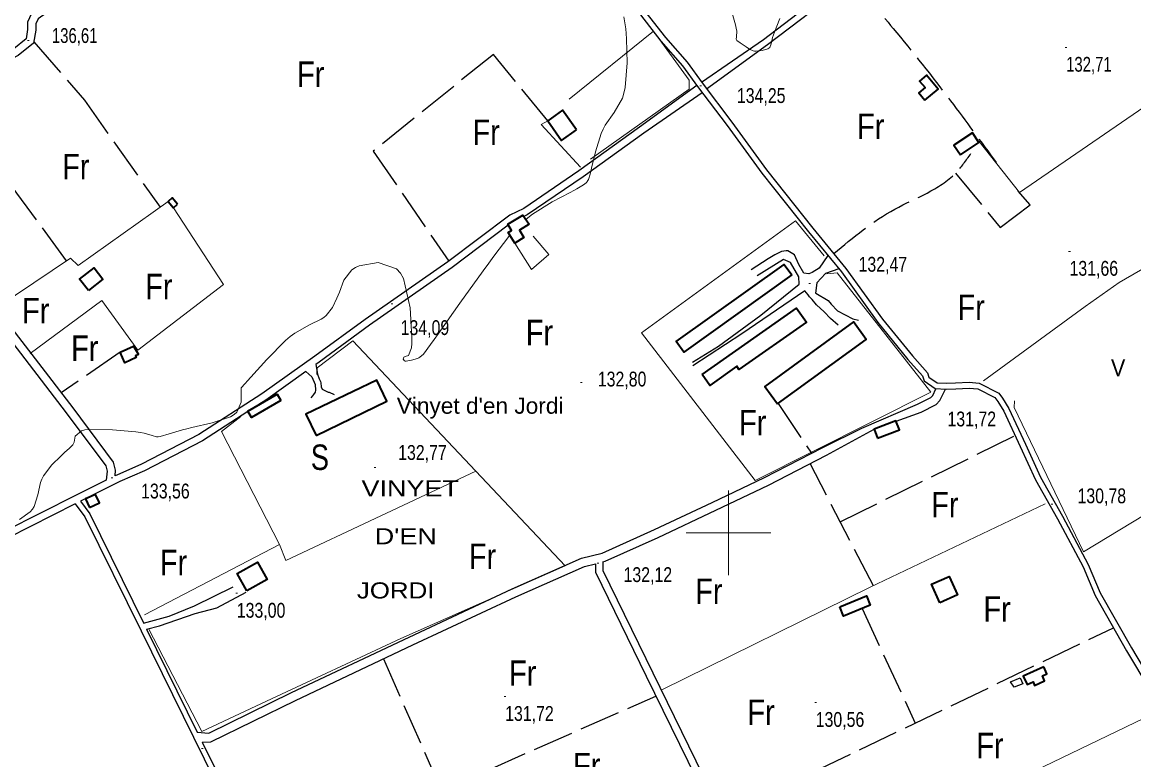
# Model space of a CAD drawing. Extents: x 483855 to 488461, y 4388206 to 4391419.
# Drawn here: x 485084 to 485739, y 4390366 to 4390801 of the extents above; entities that cross this region are included whole.
import ezdxf
from ezdxf.enums import TextEntityAlignment as Align

# ---------------------------------------------------------------- set-up
doc = ezdxf.new("R2010")
doc.units = 0
doc.header["$LTSCALE"] = 4
doc.linetypes.add('LONG_DASHED', pattern=[7.5, 6, -1.5])
for name, color, linetype, lineweight in [('1', 7, 'Continuous', 13), ('21', 7, 'Continuous', 25), ('25', 7, 'LONG_DASHED', 25), ('36', 7, 'Continuous', 25), ('38', 7, 'Continuous', 25), ('47', 7, 'Continuous', 35), ('51', 7, 'Continuous', 13), ('7', 7, 'Continuous', 13), ('9', 7, 'Continuous', 13)]:
    doc.layers.add(name, color=color, linetype=linetype, lineweight=lineweight)
doc.layers.add('31', color=7, linetype='Continuous')
doc.layers.add('5', color=7, linetype='Continuous')

msp = doc.modelspace()

# ---------------------------------------------------------------- linework, layer by layer
at = {"layer": '1'}
for p, q in [((485500, 4390525), (485500, 4390475)), ((485475, 4390500), (485525, 4390500))]:
    msp.add_line(p, q, dxfattribs=at)
at = {"layer": '21'}
msp.add_lwpolyline([(485673.31, 4390410.9), (485668.29, 4390408.94), (485666.19, 4390412.17), (485671.88, 4390414.43)], close=True, dxfattribs=at)
at = {"layer": '25'}
for p, q in [((485110.05, 4390660.3), (485037.72, 4390758.71)), ((485141.55, 4390606.36), (485106.86, 4390582.49)), ((485529.18, 4390576.09), (485548.8, 4390546.83)), ((485565.83, 4390506.52), (485668.86, 4390557.26)), ((485585.32, 4390468.79), (485548.13, 4390540.73)), ((485578.76, 4390455.3), (485610, 4390387.84)), ((485496.08, 4390333.01), (485726.76, 4390444.04)), ((485330.9, 4390348.01), (485457.19, 4390403.79))]:
    msp.add_line(p, q, dxfattribs=at)
for points in [[(485090.71, 4390789.32), (485120.57, 4390754.91), (485165.17, 4390691.87)], [(485393.49, 4390742.76), (485361.47, 4390781.94), (485290.75, 4390724.89), (485335.22, 4390660.14)], [(485633.81, 4390712.02), (485659.97, 4390679.88), (485677.65, 4390693.19), (485670.73, 4390701.38)], [(485296.72, 4390425.72), (485330.9, 4390348.01), (485230.08, 4390296.09)]]:
    msp.add_lwpolyline(points, dxfattribs=at)
at = {"layer": '36'}
for points in [[(485441.39, 4390813.87), (485460.18, 4390789.75), (485472.96, 4390775.14), (485481.68, 4390763.08), (485499.27, 4390739.93), (485519.72, 4390711.91), (485547.08, 4390677.37), (485566.47, 4390653.7), (485587.9, 4390623.88), (485605.71, 4390602.08), (485614.21, 4390592.42), (485615.19, 4390589.49), (485621.72, 4390584.93), (485628.17, 4390584.64), (485633.87, 4390584.87), (485641.67, 4390585.26), (485646.78, 4390584.82), (485656.91, 4390579.66), (485658.56, 4390577.34), (485662.1, 4390571.64), (485671.89, 4390550.8), (485680.77, 4390531.24), (485693.78, 4390508.15), (485708.83, 4390479.9), (485715.91, 4390463.03), (485734.49, 4390430.51), (485748.11, 4390407.42)], [(485443.99, 4390816.14), (485462.83, 4390791.94), (485475.66, 4390777.29), (485484.44, 4390765.13), (485502.03, 4390741.99), (485522.46, 4390713.99), (485549.76, 4390679.53), (485569.2, 4390655.8), (485590.63, 4390625.97), (485608.34, 4390604.31), (485617.25, 4390594.17), (485618.09, 4390591.66), (485622.87, 4390588.32), (485628.18, 4390588.08), (485633.71, 4390588.31), (485641.73, 4390588.71), (485647.74, 4390588.19), (485659.22, 4390582.34), (485661.43, 4390579.25), (485665.13, 4390573.29), (485675.01, 4390552.24), (485683.84, 4390532.8), (485696.8, 4390509.8), (485711.94, 4390481.38), (485719, 4390464.56), (485737.47, 4390432.24), (485751.16, 4390409.03)], [(485443.99, 4390816.14), (485462.83, 4390791.94), (485475.66, 4390777.29), (485484.44, 4390765.13), (485502.03, 4390741.99), (485522.46, 4390713.99), (485549.76, 4390679.53), (485569.2, 4390655.8), (485590.63, 4390625.97), (485608.34, 4390604.31), (485617.25, 4390594.17), (485618.09, 4390591.66), (485622.87, 4390588.32), (485628.18, 4390588.08), (485633.71, 4390588.31), (485641.73, 4390588.71), (485647.74, 4390588.19), (485659.22, 4390582.34), (485661.43, 4390579.25), (485665.13, 4390573.29), (485675.01, 4390552.24), (485683.84, 4390532.8), (485696.8, 4390509.8), (485711.94, 4390481.38), (485719, 4390464.56), (485737.47, 4390432.24), (485751.16, 4390409.03)]]:
    msp.add_lwpolyline(points, dxfattribs=at)
at = {"layer": '38'}
msp.add_line((485157.19, 4390443.11), (485186.98, 4390382.58), dxfattribs=at)
for points in [[(485311.17, 4390959), (485273.41, 4390932.69), (485228.9, 4390902.16), (485184.76, 4390872.9), (485152.54, 4390850.87), (485124.97, 4390831.4), (485089.4, 4390806.02), (485087.11, 4390800.89), (485087.12, 4390796.59), (485086.17, 4390791.06), (485078.91, 4390785.27), (485050.68, 4390770.45), (485010.21, 4390750.37), (484988.21, 4390740.68), (484987.9, 4390738), (484987.22, 4390733.35), (484988.91, 4390729.82), (485021.04, 4390685.75), (485063.44, 4390630.98), (485109.89, 4390570.75), (485133.09, 4390539.47), (485133.9, 4390536.4), (485133.44, 4390530.95)], [(485484.09, 4390765.62), (485520.58, 4390790.78), (485565.16, 4390824.83), (485603.51, 4390855.05), (485644.49, 4390882.72), (485686.53, 4390910.77), (485710.42, 4390927.08), (485719.98, 4390931.28), (485725.74, 4390931), (485729.29, 4390927.74), (485765.68, 4390872.99), (485798.54, 4390825.11), (485825.46, 4390783.37), (485847.11, 4390755.57), (485864.56, 4390728.75), (485879.65, 4390706.38)], [(485487.07, 4390761.68), (485522.88, 4390787.67), (485567.53, 4390821.78), (485605.79, 4390851.92), (485646.65, 4390879.5), (485688.7, 4390907.56), (485712.31, 4390923.68), (485720.7, 4390927.37), (485724.15, 4390927.2), (485726.32, 4390925.21), (485762.47, 4390870.82), (485795.31, 4390822.96), (485822.3, 4390781.12), (485843.95, 4390753.32), (485861.33, 4390726.61), (485876.45, 4390704.2), (485896.67, 4390661.98), (485921.44, 4390613.92), (485950.81, 4390554.58), (485972.61, 4390514.7)], [(485146.87, 4390841.02), (485127.73, 4390827.51), (485093.22, 4390802.89), (485091.88, 4390799.88), (485091.89, 4390796.19), (485090.56, 4390788.47), (485081.53, 4390781.26), (485052.84, 4390766.21), (485012.23, 4390746.05), (484992.63, 4390737.42), (484992.63, 4390737.39), (484992.15, 4390734.1), (484993.02, 4390732.28), (485024.85, 4390688.62), (485067.21, 4390633.89), (485113.69, 4390573.63), (485137.47, 4390541.57), (485138.72, 4390536.82), (485138.44, 4390533.46)], [(485481.25, 4390763.68), (485447.59, 4390739.09), (485411.85, 4390713.31), (485379.33, 4390691.05), (485371.08, 4390687.21), (485334.74, 4390659.77), (485285.97, 4390625.78), (485256.3, 4390604.06), (485224.98, 4390581.8), (485188.03, 4390557.89), (485154.16, 4390540.35), (485139.61, 4390534.03), (485138.44, 4390533.46)], [(485484.53, 4390759.34), (485450.1, 4390735.6), (485414.32, 4390709.79), (485381.47, 4390687.3), (485379.43, 4390686.35)], [(485370.25, 4390681.19), (485337.27, 4390656.29), (485288.47, 4390622.28), (485258.82, 4390600.57), (485256.81, 4390599.14)], [(485558.57, 4390663.35), (485553.34, 4390655.85), (485549.22, 4390653.3), (485547.27, 4390652.69), (485544.42, 4390652.99), (485541.34, 4390658.01), (485538.85, 4390663.78), (485534.95, 4390666.17), (485533.97, 4390666.17), (485531.27, 4390665.79), (485527.3, 4390663.76), (485523.33, 4390661.5), (485513.36, 4390655.04)], [(485478.79, 4390600.6), (485494.08, 4390610.07), (485519.03, 4390628.19), (485541.58, 4390646.61), (485541.35, 4390650.88), (485536.61, 4390659.28), (485532.4, 4390660.99), (485516.89, 4390651.52)], [(485564.95, 4390655.57), (485557.17, 4390652.71), (485551.93, 4390647.3), (485551.19, 4390641.3), (485551.42, 4390641.22), (485558.7, 4390636.81), (485560.43, 4390634.79), (485564.11, 4390630.82), (485573.19, 4390626.1), (485576.5, 4390625.28)], [(485564.57, 4390622.41), (485560.14, 4390626.31), (485556.31, 4390630.28), (485551.88, 4390634.32), (485549.25, 4390637.39), (485547.67, 4390639.12), (485546.84, 4390640.24), (485545.04, 4390642.56), (485507.8, 4390617.15), (485479.02, 4390598.35)], [(485256.81, 4390599.14), (485257.81, 4390593.48), (485258.94, 4390590.78), (485259.7, 4390589.06), (485259.85, 4390588.31), (485260.08, 4390585.98), (485260.68, 4390584.71), (485264.21, 4390582.92), (485264.66, 4390582.77), (485267.73, 4390581.57)], [(485251.05, 4390595.05), (485227.4, 4390578.24), (485223.4, 4390575.65)], [(485251.05, 4390595.05), (485254.52, 4390591.83), (485256.4, 4390587.48), (485256.63, 4390584.1), (485256.48, 4390582.9), (485255.51, 4390581.55), (485254.98, 4390580.73), (485253.86, 4390579.52)], [(485186.98, 4390382.58), (485193.76, 4390381.82), (485242.63, 4390405.8), (485311.94, 4390438.57), (485372.63, 4390466.9), (485413.42, 4390485.02), (485425.63, 4390488.04), (485456.49, 4390501.91), (485490.32, 4390517.92), (485521.28, 4390532.56), (485555.5, 4390550.3), (485578.44, 4390561.59), (485611.32, 4390575.74), (485619.18, 4390579.72), (485620.3, 4390580.88), (485622.05, 4390584.92)], [(485598.68, 4390565.7), (485613.49, 4390571.11), (485622.26, 4390575.55), (485624.51, 4390577.88), (485627.82, 4390584.67)], [(485216.92, 4390571.46), (485190.19, 4390554.16), (485156.01, 4390536.46), (485141.43, 4390530.13), (485118.17, 4390518.56)], [(485425.89, 4390482.84), (485427.3, 4390483.19), (485458.63, 4390497.27), (485492.51, 4390513.3), (485523.55, 4390527.98), (485557.8, 4390545.74), (485585.79, 4390560.99)], [(485133.44, 4390530.95), (485115.7, 4390522.14), (485073.73, 4390500.91), (485031.83, 4390479.77), (485010.32, 4390468.03), (485001.93, 4390465.01), (484981.84, 4390460.24)], [(485115.19, 4390517.05), (485075.67, 4390497.07), (485033.83, 4390475.96), (485012.09, 4390464.09), (485003.16, 4390460.88), (484947.91, 4390447.77), (484892.69, 4390433.86), (484854.23, 4390425.4), (484823.48, 4390418.15)], [(485115.19, 4390517.05), (485120.9, 4390509.39), (485153.94, 4390442.23), (485197.14, 4390354.46), (485231.39, 4390286.11), (485274.74, 4390199.39), (485308.3, 4390134.85), (485322.07, 4390107.8), (485344.04, 4390065.9), (485357.15, 4390034.19)], [(485118.17, 4390518.56), (485123.73, 4390511.12), (485155.3, 4390446.94)], [(485189.92, 4390376.61), (485195.01, 4390376.74), (485244.85, 4390401.2), (485314.11, 4390433.94), (485374.75, 4390462.25), (485415.08, 4390480.17), (485421.55, 4390481.77)], [(485421.55, 4390481.77), (485421.57, 4390476.82), (485451.45, 4390415.49), (485480.94, 4390355.34), (485505.34, 4390302.62), (485511.39, 4390287.91), (485519.02, 4390277.43)], [(485425.89, 4390482.84), (485425.92, 4390477.83), (485455.36, 4390417.4), (485484.87, 4390357.21), (485509.33, 4390304.37), (485515.21, 4390290.05), (485521.05, 4390282.03), (485536.34, 4390285.07), (485552.75, 4390289.3), (485561.08, 4390288.86), (485572.58, 4390290.77), (485576.97, 4390293.53), (485583.14, 4390290.64), (485593.96, 4390282.92), (485604.49, 4390279.94)], [(485155.39, 4390446.78), (485170.58, 4390450.81), (485185.5, 4390456.99), (485208.13, 4390468.13)], [(485157.19, 4390443.11), (485164.74, 4390445.1), (485185.88, 4390452.41), (485198.63, 4390455.81), (485215.94, 4390464.99)], [(485189.92, 4390376.61), (485200.1, 4390355.93), (485234.34, 4390287.59), (485277.68, 4390200.89), (485311.23, 4390136.36), (485325, 4390109.31), (485347.03, 4390067.3), (485360.2, 4390035.45)]]:
    msp.add_lwpolyline(points, dxfattribs=at)
at = {"layer": '38', "linetype": 'LONG_DASHED'}
for points in [[(485572.68, 4390825.83), (485596.99, 4390797.25), (485630.74, 4390754.62), (485657.73, 4390718.13)], [(485562, 4390664.6), (485597.99, 4390690.73), (485633.81, 4390712.02), (485642.8, 4390723.51)], [(485014.04, 4390465.16), (485018.06, 4390459.11), (485044.44, 4390383.92), (485062.76, 4390327.24), (485083.13, 4390259.98), (485109.98, 4390167.39)]]:
    msp.add_spline(points, degree=3, dxfattribs=at)
at = {"layer": '47'}
for points in [[(485615.74, 4390755.05), (485623.46, 4390761.51), (485616.67, 4390769.61), (485612.57, 4390766.17), (485615.78, 4390762.34), (485612.13, 4390759.32)], [(485410.46, 4390737.46), (485402.25, 4390749), (485393.49, 4390742.76), (485401.7, 4390731.22)], [(485636.57, 4390722.68), (485647.48, 4390730), (485643.68, 4390735.67), (485632.77, 4390728.35)], [(485175.43, 4390693.57), (485172.26, 4390697.3), (485169.88, 4390695.28), (485173.05, 4390691.55)], [(485382.64, 4390681.83), (485376.87, 4390678.29), (485379.51, 4390673.97), (485374.06, 4390670.64), (485370.19, 4390676.97), (485372.14, 4390678.16), (485369.93, 4390681.78), (485378.81, 4390687.21)], [(485537.29, 4390651.93), (485473.58, 4390606.48), (485469.17, 4390612.66), (485532.88, 4390658.11)], [(485123.01, 4390642.77), (485117.74, 4390649.47), (485126.21, 4390656.13), (485131.48, 4390649.43)], [(485484.51, 4390593.33), (485540.1, 4390632.35), (485545.86, 4390624.13), (485506.13, 4390596.29), (485504.85, 4390598.1), (485488.98, 4390586.89)], [(485528.94, 4390575.92), (485581.15, 4390613.93), (485573.65, 4390624.23), (485521.44, 4390586.22)], [(485152.47, 4390605.16), (485150.68, 4390604.33), (485151.14, 4390603.31), (485144.31, 4390600.24), (485141.55, 4390606.36), (485149.53, 4390609.98)], [(485257.05, 4390557.4), (485298.8, 4390577.51), (485292.78, 4390590.01), (485251.03, 4390569.9)], [(485236.23, 4390577.99), (485219.03, 4390567.95), (485216.82, 4390571.74), (485234.02, 4390581.78)], [(485587.86, 4390555.69), (485600.64, 4390560.68), (485598.57, 4390565.98), (485585.79, 4390560.99)], [(485123.52, 4390514.95), (485129.41, 4390517.57), (485127.18, 4390522.6), (485121.29, 4390519.98)], [(485216.24, 4390465.82), (485210.54, 4390475.97), (485222.51, 4390482.7), (485228.21, 4390472.55)], [(485624.48, 4390458.76), (485619.63, 4390469.69), (485630, 4390474.29), (485634.85, 4390463.36)], [(485565.52, 4390456.26), (485581.26, 4390462.74), (485583.52, 4390457.26), (485567.78, 4390450.78)], [(485685.83, 4390421.05), (485673.61, 4390415.48), (485675.85, 4390410.54), (485679.4, 4390412.16), (485680.34, 4390410.08), (485686.24, 4390412.75), (485684.9, 4390415.69), (485687.48, 4390416.86)]]:
    msp.add_lwpolyline(points, close=True, dxfattribs=at)
at = {"layer": '51'}
for points in [[(485647.59, 4390730.5), (485671.34, 4390700.6), (485811.68, 4390796.85), (485779.43, 4390843.01), (485738.52, 4390903.63), (485723.64, 4390922.96), (485696.65, 4390911.13), (485646.74, 4390879.02), (485626.34, 4390865.27)], [(485418.74, 4390720.22), (485476.8, 4390761.5), (485476.87, 4390766.67), (485455.82, 4390795.59), (485406.15, 4390755.61)], [(485393.49, 4390742.76), (485389.67, 4390740.65), (485412.74, 4390715.48), (485412.74, 4390715.48)], [(485650.22, 4390589.55), (485710.16, 4390633.45), (485730.16, 4390647.44), (485814.47, 4390696.19), (485862.96, 4390723.35)], [(485068.94, 4390632.86), (485112.32, 4390661.81), (485116.91, 4390657.46), (485169.91, 4390695.25)], [(485088.64, 4390605.73), (485130.82, 4390636.86), (485151.94, 4390607.71), (485202.52, 4390646.35), (485173.05, 4390691.55)], [(485556.33, 4390663.21), (485539.49, 4390683.89), (485448.68, 4390617.87), (485515.74, 4390530.89), (485619.1, 4390582.9), (485564.07, 4390653.17), (485557.92, 4390652.56)], [(485374.06, 4390670.64), (485383.89, 4390655.12), (485394.15, 4390663.99), (485384.9, 4390674.71)], [(485257.44, 4390593.26), (485257.58, 4390597.23), (485278.71, 4390613.02), (485403.75, 4390480.52), (485307.05, 4390437.76), (485227.9, 4390400.8), (485189.67, 4390382.81), (485158.22, 4390443.52)], [(485817.11, 4390554.12), (485709.04, 4390488.68), (485668.32, 4390573.83), (485668.54, 4390577.8)], [(485212.67, 4390568.54), (485201.23, 4390559.71), (485235.4, 4390493.15)], [(485155.88, 4390451.69), (485235.4, 4390493.15), (485239.31, 4390483.63), (485351.16, 4390536.26)], [(485460.73, 4390407.48), (485583.5, 4390467.92), (485686.57, 4390516.99)], [(485750.16, 4390393.33), (485599.65, 4390320.77), (485525.9, 4390283.89)]]:
    msp.add_lwpolyline(points, dxfattribs=at)
at = {"layer": '7'}
for p, q in [((485087.01, 4390790.19), (485088.01, 4390790.19)), ((485698.38, 4390786.09), (485699.38, 4390786.09)), ((485483.05, 4390763.38), (485484.05, 4390763.38)), ((485700.38, 4390665.85), (485701.38, 4390665.85)), ((485547.23, 4390646.84), (485548.23, 4390646.84)), ((485301.28, 4390634.96), (485302.28, 4390634.96)), ((485412.83, 4390588.64), (485413.83, 4390588.64)), ((485625.27, 4390584.56), (485626.27, 4390584.56)), ((485136.34, 4390532.45), (485137.34, 4390532.45)), ((485291.23, 4390538.55), (485292.23, 4390538.55)), ((485690.12, 4390516.78), (485691.12, 4390516.78)), ((485422.68, 4390482.13), (485423.68, 4390482.13)), ((485209.82, 4390464.31), (485210.82, 4390464.31)), ((485367.9, 4390403.5), (485368.9, 4390403.5)), ((485550.86, 4390399.98), (485551.86, 4390399.98)), ((485189.49, 4390372.9), (485190.49, 4390372.9))]:
    msp.add_line(p, q, dxfattribs=at)
at = {"layer": '9'}
for points in [[(485530.16, 4390802.99), (485527.03, 4390795.09), (485526.42, 4390793.37), (485525.93, 4390791.86), (485525.12, 4390788.12), (485524.25, 4390786.05), (485523.73, 4390785.59), (485523.09, 4390785.19), (485519.76, 4390784.14), (485516.11, 4390783.85), (485515.27, 4390783.91), (485514.5, 4390784.04), (485512.33, 4390785.04), (485510.46, 4390786.46), (485509.88, 4390786.86), (485509.27, 4390787.26), (485506.84, 4390788.7), (485504.93, 4390790.14), (485504.65, 4390790.52), (485504.48, 4390790.91), (485504.74, 4390792.27), (485504.81, 4390795.66), (485504.52, 4390797.31), (485504.08, 4390799.29), (485501.4, 4390809.02)], [(485438.37, 4390804.1), (485439.55, 4390797.01), (485439.77, 4390794.24), (485439.96, 4390791.11), (485440.27, 4390776.92), (485439.12, 4390762.4), (485438.39, 4390759.08), (485437.48, 4390756.07), (485432.7, 4390747.69), (485427.38, 4390740.25), (485426.14, 4390737.82), (485424.98, 4390735.23), (485421.63, 4390724.55), (485419.35, 4390714.9), (485418.87, 4390712.96), (485418.46, 4390711.33), (485417.53, 4390708.11), (485416.79, 4390706.94), (485416.49, 4390706.61), (485416.15, 4390706.28), (485414.61, 4390705.08), (485410.69, 4390702.79), (485408.85, 4390701.79), (485406.69, 4390700.61), (485396.19, 4390695.02), (485384.6, 4390687.85), (485381.76, 4390685.69), (485380.59, 4390684.71)], [(485371.23, 4390675.27), (485370.68, 4390674.7), (485361.77, 4390663.02), (485358.75, 4390658.93), (485355.49, 4390654.46), (485341.75, 4390635.24), (485329.15, 4390617.46), (485326.6, 4390613.91), (485324.48, 4390610.96), (485320.22, 4390605.23), (485318.2, 4390603.56), (485317.48, 4390603.16), (485316.69, 4390602.78), (485313.27, 4390601.65), (485310.15, 4390601.15), (485309.56, 4390601.18), (485309.08, 4390601.28), (485308.32, 4390602.23), (485308.8, 4390603.42), (485309.11, 4390603.68), (485309.49, 4390603.9)], [(485309.49, 4390603.9), (485311.5, 4390604.42), (485313.17, 4390608.9), (485313.35, 4390611.62), (485313.39, 4390614.99), (485312.51, 4390632.48), (485308.57, 4390649.78), (485306.69, 4390653.03), (485304.46, 4390655.6), (485293.57, 4390659.3), (485282.5, 4390657.3), (485280.16, 4390656.27), (485278.13, 4390655.04), (485273.45, 4390648.89), (485270.81, 4390641.86), (485270.07, 4390640.07), (485269.33, 4390638.35), (485266.63, 4390632.72), (485262.9, 4390628), (485261.51, 4390626.86), (485259.97, 4390625.79), (485253.11, 4390622.5), (485244.48, 4390617.66), (485241.81, 4390615.61), (485239.03, 4390613.25), (485228.02, 4390602.17), (485218.54, 4390591.64), (485216.73, 4390589.63), (485215.27, 4390588.02), (485212.97, 4390585.46), (485212.97, 4390585.46), (485212.97, 4390585.46), (485212.97, 4390585.46), (485212.97, 4390585.46), (485212.97, 4390584.15), (485212.97, 4390583.33), (485212.97, 4390582.3), (485212.98, 4390576.94), (485210.36, 4390571.02), (485208.7, 4390569.64), (485206.64, 4390568.38), (485195.84, 4390564.78), (485183.8, 4390562.05), (485180.95, 4390561.33), (485178.32, 4390560.64), (485170.57, 4390558.28), (485165.14, 4390556.77), (485163.97, 4390556.61), (485162.94, 4390556.56), (485160.41, 4390557.3), (485155.85, 4390558.72), (485153.54, 4390559.09), (485150.78, 4390559.46), (485137.03, 4390560.74), (485123.51, 4390560.91), (485120.9, 4390560.58), (485118.77, 4390560.1), (485115.18, 4390556.99), (485114.43, 4390553.36), (485114.09, 4390552.54), (485113.7, 4390551.79), (485111.84, 4390549.78), (485108.88, 4390547.37), (485107.81, 4390546.37), (485106.62, 4390545.23), (485101.42, 4390539.95), (485096.52, 4390533.47), (485095.53, 4390531.58), (485094.7, 4390529.65), (485093.02, 4390522.33), (485090.97, 4390515.49), (485089.91, 4390513.86), (485088.63, 4390512.34), (485082.23, 4390507.82)]]:
    msp.add_lwpolyline(points, dxfattribs=at)

# ---------------------------------------------------------------- texts
at = {"layer": '31'}
for s, height, width, p in [('Fr', 15, 0.85, (485253.84, 4390762.78)), ('Fr', 15, 0.85, (485357.24, 4390728.52)), ('Fr', 15, 0.85, (485583.79, 4390732.02)), ('Fr', 15, 0.85, (485115.5, 4390708.25)), ('Fr', 15, 0.85, (485164.41, 4390637.65)), ('Fr', 15, 0.85, (485091.89, 4390623.41)), ('Fr', 15, 0.85, (485642.98, 4390625.35)), ('Fr', 15, 0.85, (485388.62, 4390610.52)), ('Fr', 15, 0.85, (485120.76, 4390601.33)), ('V', 10, 0.95, (485729.54, 4390592.24)), ('Fr', 15, 0.85, (485514.24, 4390557.35)), ('S', 15, 0.8, (485259.28, 4390537.02)), ('Fr', 15, 0.85, (485627.48, 4390509.06)), ('Fr', 15, 0.85, (485355.11, 4390478.58)), ('Fr', 15, 0.85, (485173.08, 4390474.95)), ('Fr', 15, 0.85, (485488.44, 4390458.03)), ('Fr', 15, 0.85, (485658.22, 4390447.55)), ('Fr', 15, 0.85, (485378.74, 4390409.8)), ('Fr', 15, 0.85, (485519.18, 4390386.73)), ('Fr', 15, 0.85, (485654.03, 4390367.16)), ('Fr', 15, 0.85, (485416.47, 4390355.28))]:
    msp.add_text(s, height=height, dxfattribs=dict(at, width=width)).set_placement(p, align=Align.CENTER)
at = {"layer": '5', "width": 1.05}
msp.add_text("Vinyet d'en Jordi", height=9.5, dxfattribs=at).set_placement((485304.55, 4390570.14))
at = {"layer": '5'}
for s, width, p in [('VINYET ', 1.25, (485345.57, 4390521.4)), (" D'EN ", 1.25, (485332.56, 4390493.21)), (' JORDI', 1.2, (485326.79, 4390461.27))]:
    msp.add_text(s, height=9.5, dxfattribs=dict(at, width=width)).set_placement(p, align=Align.RIGHT)
at = {"layer": '7'}
for s, width, p in [('136,61', 0.75, (485101.41, 4390788.66)), ('132,71', 0.75, (485698.88, 4390771.72)), ('134,25', 0.8, (485504.94, 4390753.29)), ('132,47', 0.8, (485576.6, 4390653.86)), ('131,66', 0.8, (485700.88, 4390651.48)), ('134,09', 0.8, (485306.84, 4390616.54)), ('132,80', 0.8, (485422.99, 4390586.21)), ('131,72', 0.8, (485628.98, 4390562.7)), ('132,77', 0.8, (485305.37, 4390542.94)), ('133,56', 0.8, (485153.95, 4390520.22)), ('130,78', 0.8, (485705.59, 4390517.39)), ('132,12', 0.8, (485438.15, 4390470.97)), ('133,00', 0.8, (485210.32, 4390449.94)), ('131,72', 0.8, (485368.4, 4390389.13)), ('130,56', 0.8, (485551.36, 4390385.61))]:
    msp.add_text(s, height=8.75, dxfattribs=dict(at, width=width)).set_placement(p)

doc.saveas('drawing.dxf')
